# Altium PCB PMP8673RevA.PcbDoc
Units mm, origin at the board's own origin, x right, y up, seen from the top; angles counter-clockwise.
Board outline 96.52 x 68.58 mm, 4 copper layers (Top Layer, Layer2, Layer3, Bottom Layer), stack 2.424 mm thick; 65 components, 30 nets, 170 pads, 151 vias.
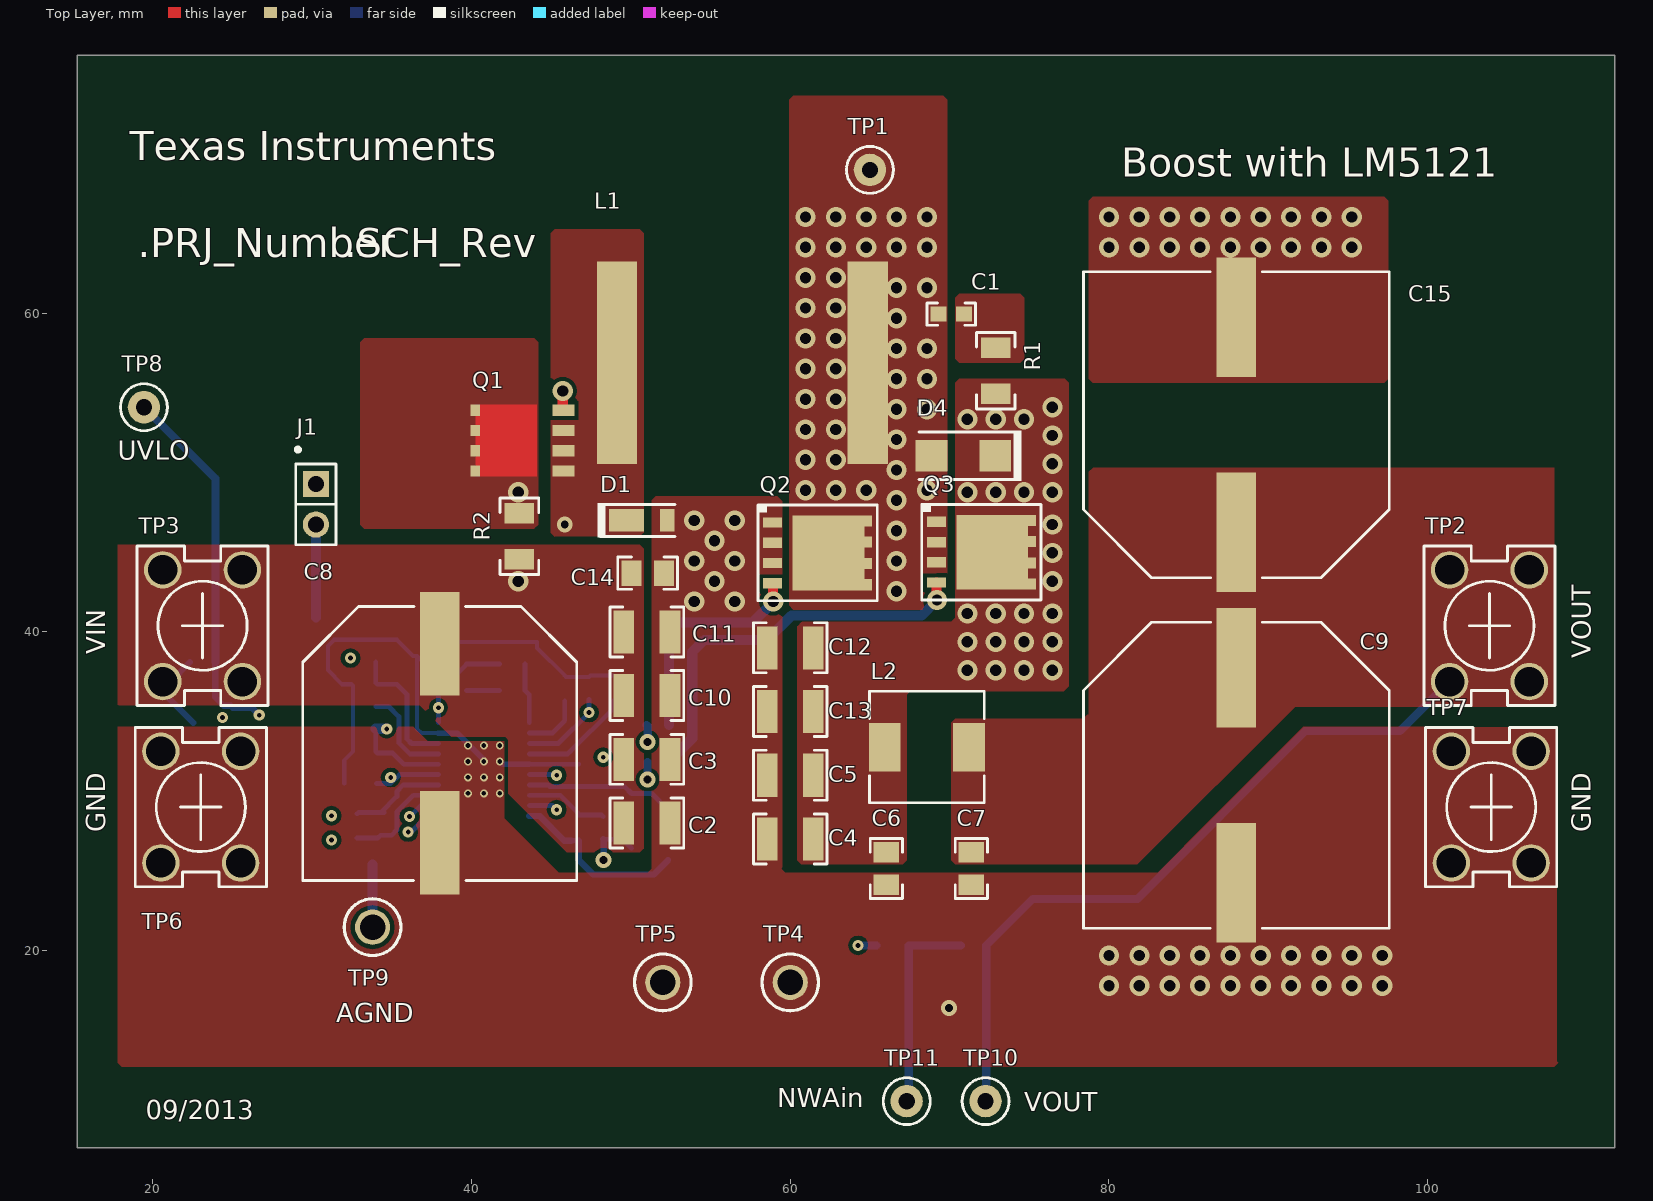
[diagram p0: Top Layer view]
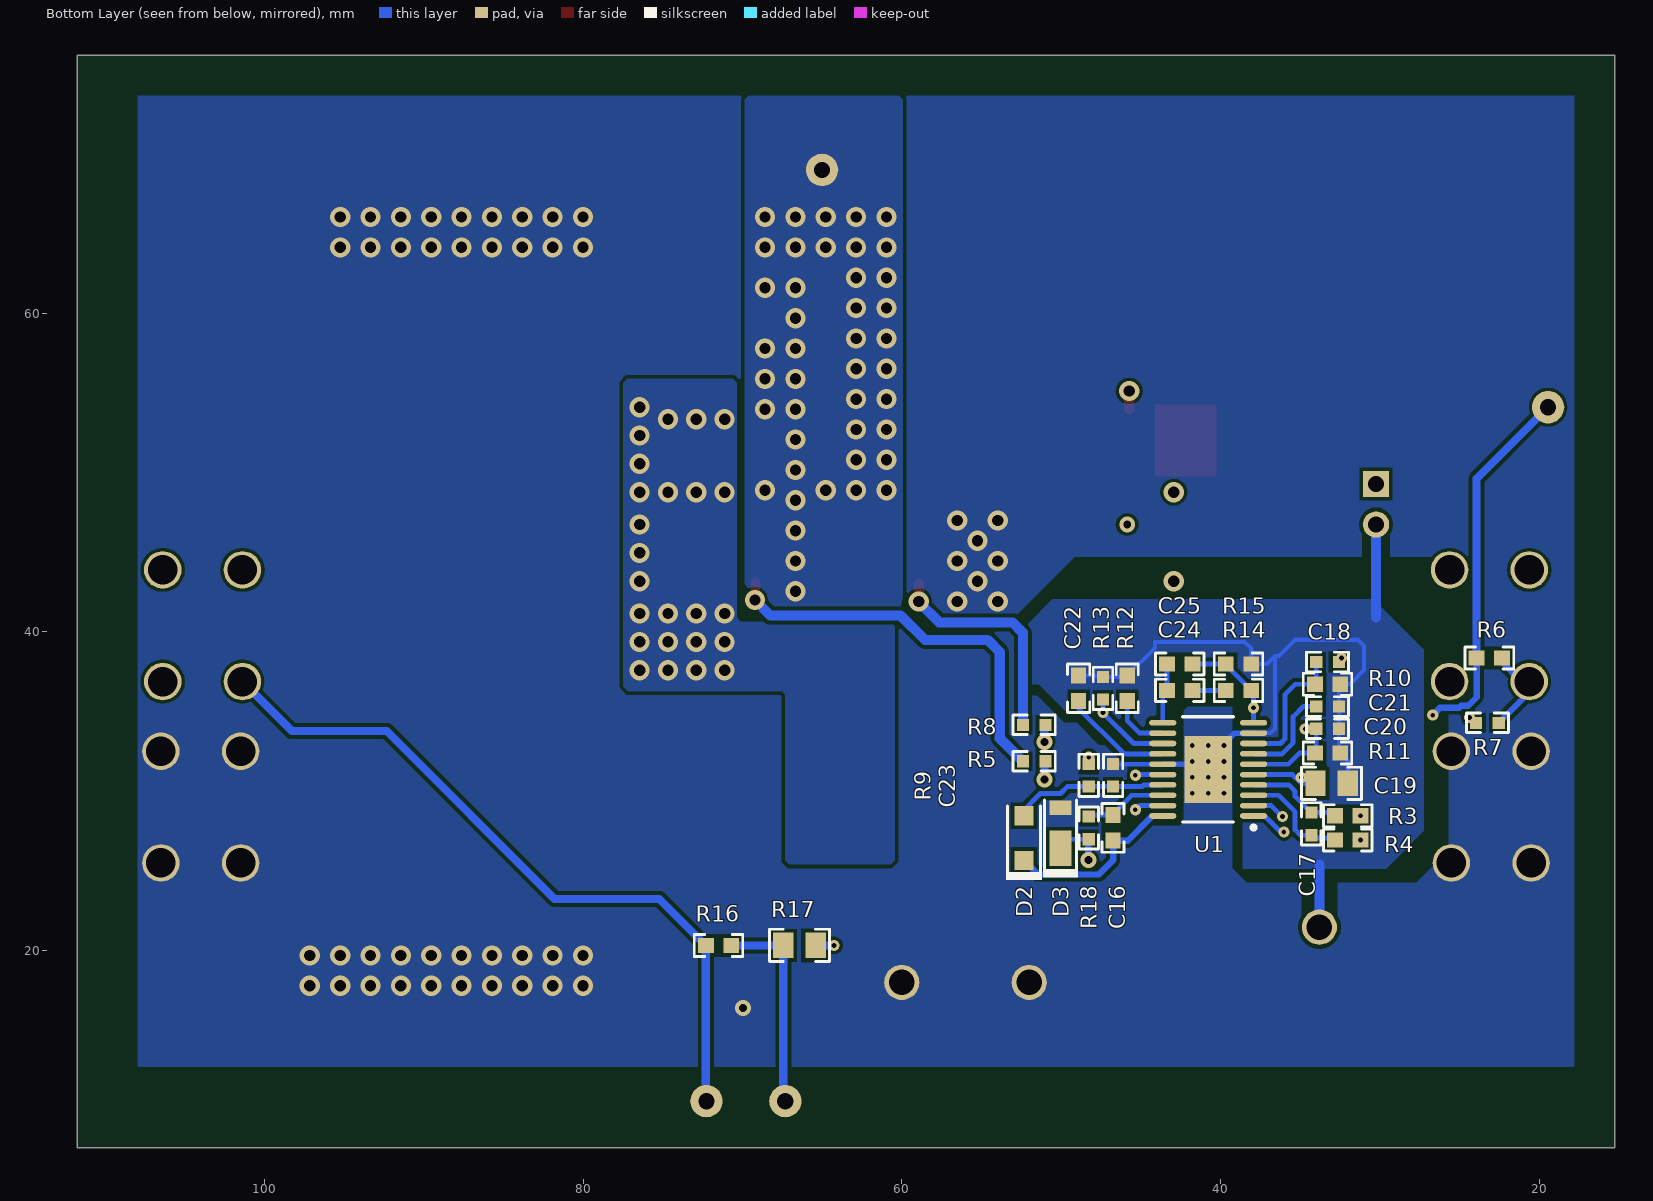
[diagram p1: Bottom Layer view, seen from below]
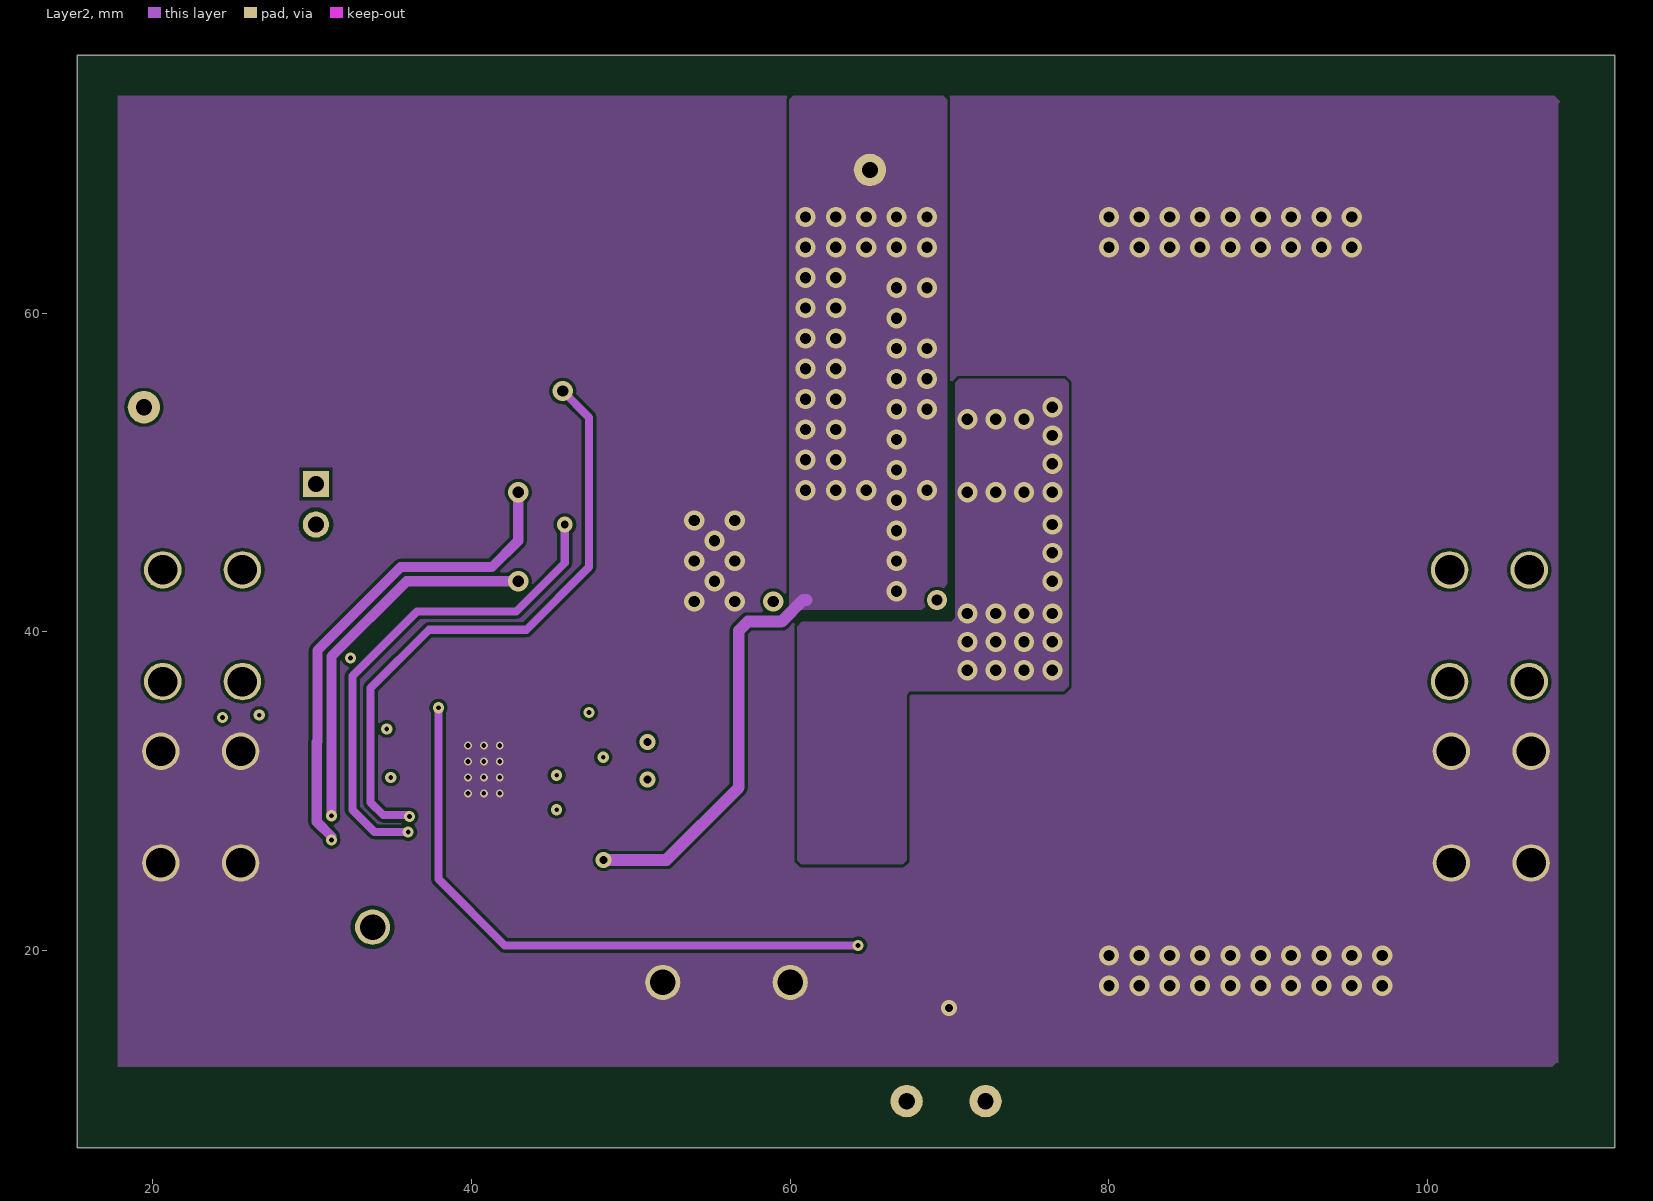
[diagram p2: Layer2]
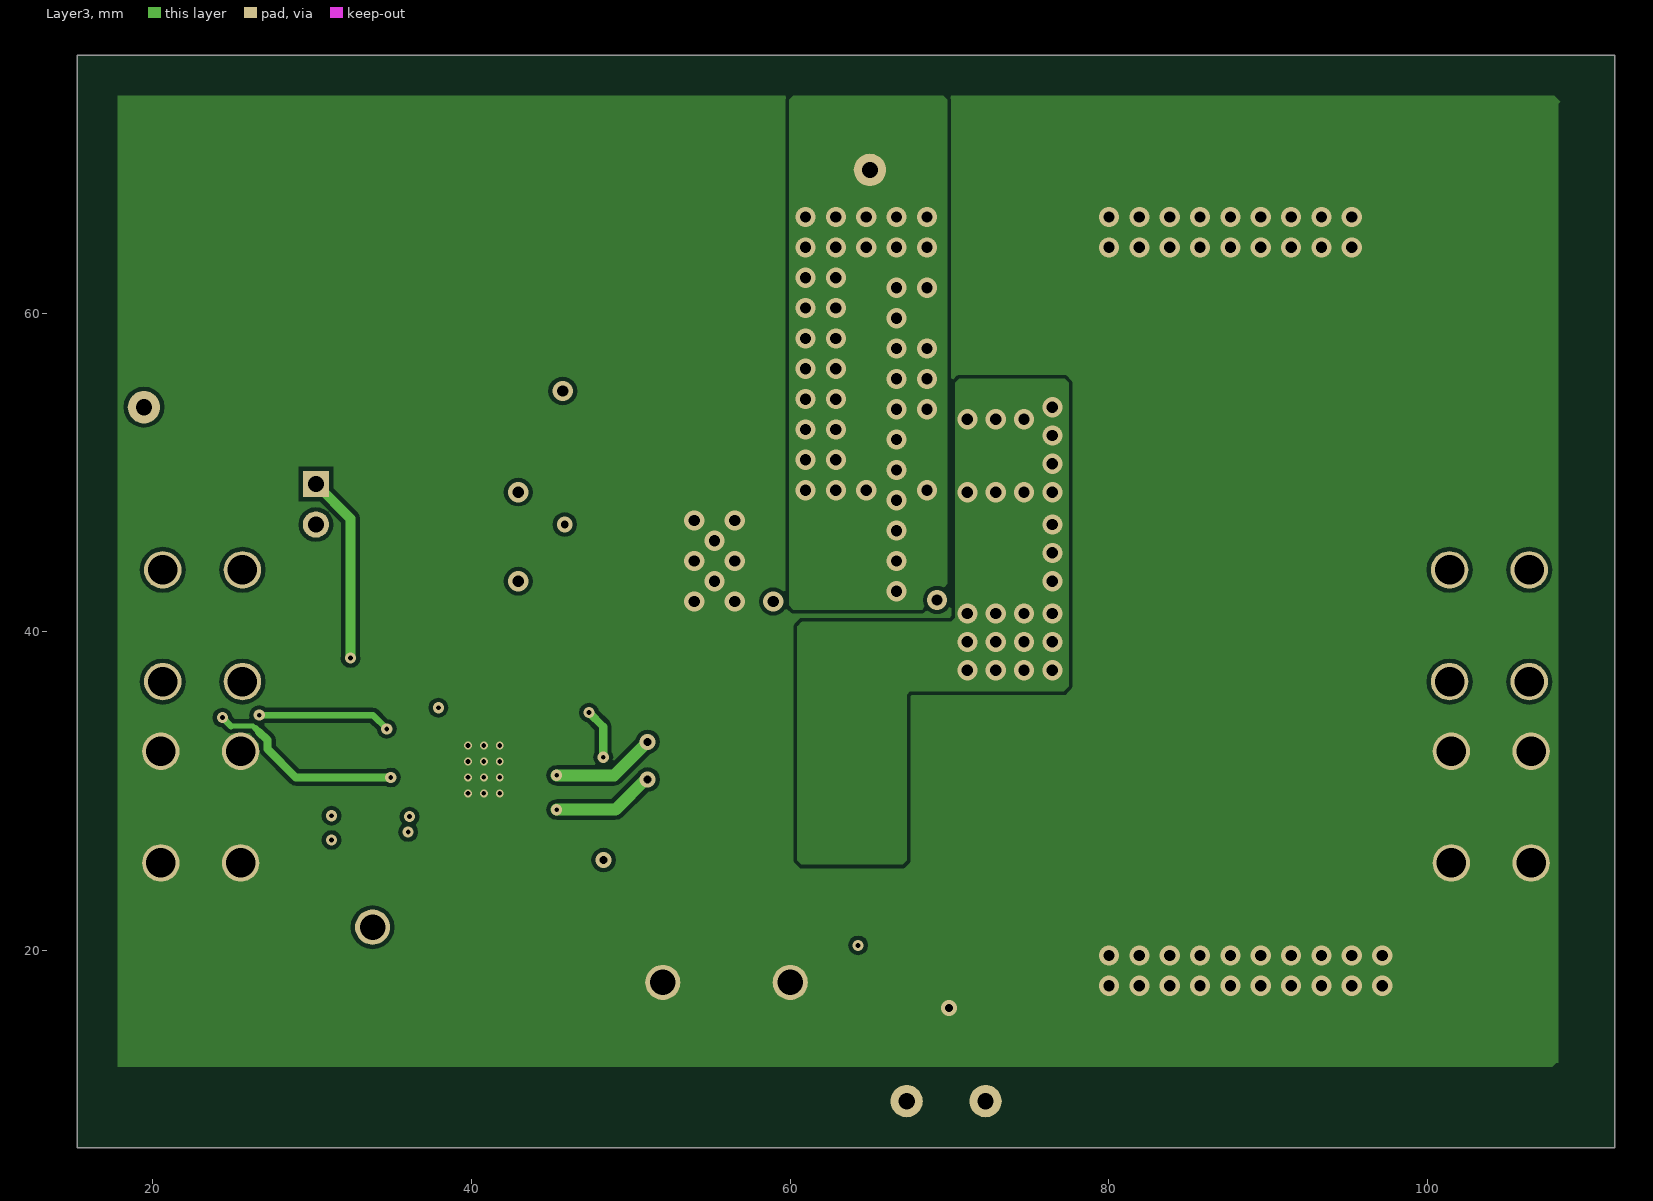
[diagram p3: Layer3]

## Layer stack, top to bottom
Top Solder: solder mask 0.0102, Solder Resist, Dk 3.5
Top Layer: signal copper 0.07
Dielectric1: core 1.5037, FR-4, Dk 4.8
Layer2: signal copper 0.07
Dielectric2: prepreg 0.32, FR-4, Dk 4.8
Layer3: signal copper 0.07
Dielectric3: core 0.32, FR-4, Dk 4.8
Bottom Layer: signal copper 0.07
Bottom Solder: solder mask 0.0102, Solder Resist, Dk 3.5

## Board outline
15.24,7.62 111.76,7.62 111.76,76.2 15.24,76.2

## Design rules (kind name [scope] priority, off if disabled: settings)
AcuteAngle [All] p1: minimum=4.50000000000000E+0001 checktracksonly=FALSE
AssemblyTestPointUsage [All] p1: valid=2
Clearance Clearance_Poly [InPolygon vs OnBottomLayer] p1: gap=0.254
Clearance Clearance_L3 [OnLayer('Layer3')] p2: gap=0.254
Clearance Clearance_L2 [(OnLayer('Layer 2'))] p3: gap=0.254
Clearance Clearance_Top [(OnLayer('Top Layer'))] p4: gap=0.254
Clearance Clearance_BoardEdge_MountingHoles [OnCopper and InComponentClass('Mounting Holes') vs IsKeepOut] p5: gap=1.016
Clearance Clearance_BoardEdge_Poly [OnCopper and InPoly vs IsKeepOut] p6: gap=0.635
Clearance Clearance_BoardEdge [OnCopper and Not InComponentClass('Logo') and not InComponentClass('FiducialMark') and not InRegion(1000,500,4000,800) and Not IsKeepout vs IsKeepOut] p7: gap=1.905
Clearance [All] p8: gap=0.201
ComponentClearance ComponentClearance_ScrewToNut [(HasFootprint('NY PMS 440 0025 PH')) vs (HasFootprint('Keystone_1902C'))] p1 off: gap=0.127 collisioncheckmode=3 verticalgap=0.254 showdistances=FALSE
ComponentClearance ComponentClearance_MountingHoles [InComponentClass('Mounting Holes')] p2 off: gap=6.35 collisioncheckmode=3 verticalgap=2540 showdistances=FALSE
ComponentClearance ComponentClearance_SmallPassives [HasFootprint('0201*') or HasFootprint('0402*') or HasFootprint('0508') or HasFootprint('0603*') or HasFootprint('0612') or HasFootprint('0805*') or HasFootprint('0815*') or HasFootprint('0830*') or HasFootprint('1206*') or HasFootprint('1210*') or HasFootprint('1808*') or HasFootprint('1812*') or HasFootprint('1825*') or HasFootprint('2010*') or HasFootprint('2220*') or HasFootprint('2225*') or HasFootprint('2512*') or HasFootprint('2728*') or HasFootprint('3518*') vs HasFootprint('0201*') or HasFootprint('0402*') or HasFootprint('0508') or HasFootprint('0603*') or HasFootprint('0612') or HasFootprint('0805*') or HasFootprint('0815*') or HasFootprint('0830*') or HasFootprint('1206*') or HasFootprint('1210*') or HasFootprint('1808*') or HasFootprint('1812*') or HasFootprint('1825*') or HasFootprint('2010*') or HasFootprint('2220*') or HasFootprint('2225*') or HasFootprint('2512*') or HasFootprint('2728*') or HasFootprint('3518*')] p3 off: gap=0.508 collisioncheckmode=3 verticalgap=0.254 showdistances=FALSE
ComponentClearance ComponentClearance_THtoSMT [IsThruComponent vs IsSMTComponent] p4 off: gap=2.54 collisioncheckmode=3 verticalgap=2540 showdistances=FALSE
ComponentClearance ComponentClearance_THtoTH [IsThruComponent vs IsThruComponent] p5 off: gap=3 collisioncheckmode=3 verticalgap=2540 showdistances=FALSE
ComponentClearance [All] p6 off: gap=1.016 collisioncheckmode=3 verticalgap=0.254 showdistances=FALSE
DiffPairsRouting [All] p1: maxlimit=2.54 minlimit=0.254 mostfreqgap=0.254 toplayer_minwidth=0.381 toplayer_maxwidth=0.381 toplayer_prefwidth=0.381 midlayer1_minwidth=0.381 midlayer1_maxwidth=0.381 midlayer1_prefwidth=0.381 midlayer2_minwidth=0.381 midlayer2_maxwidth=0.381 midlayer2_prefwidth=0.381 bottomlayer_minwidth=0.381 bottomlayer_maxwidth=0.381 bottomlayer_prefwidth=0.381 maxuncoupledlength=25.4
FabricationTestPointUsage TestPointUsage [All] p1: valid=2 allowmultiple=FALSE
FabricationTestpoint Testpoint [All] p1: side=3 testpointundercomponent=TRUE minsize=1.016 maxsize=2.54 preferedsize=1.524 minholesize=0 maxholesize=1.016 preferedholesize=0.813 testpointgrid=0.025 allowsidetop=TRUE allowsidebottom=TRUE usegrid=TRUE gridtolerance=0
FanoutControl Fanout_LCC [IsLCC] p1: bgadir=Out bgaviamode=Centered fanoutstyle=Auto fanoutdirection=Alternating viagrid=0.025 // Fanout_LCC (Default Rule)
FanoutControl Fanout_BGA [IsBGA] p2: bgadir=Out bgaviamode=Centered fanoutstyle=Auto fanoutdirection=Alternating viagrid=0.025 // Fanout_BGA (Default Rule)
FanoutControl Fanout_Default [All] p4: bgadir=Out bgaviamode=Centered fanoutstyle=Auto fanoutdirection=Alternating viagrid=0.025 // Fanout_Default (Default Rule)
FanoutControl Fanout_Small [(CompPinCount < 5)] p5: bgadir=Out bgaviamode=Centered fanoutstyle=Auto fanoutdirection=OutThenIn viagrid=0.025 // Fanout_Small (Default Rule)
HoleSize [All] p1: absolutevalues=TRUE maxlimit=6.375 minlimit=0.203 maxpercent=80.000 minpercent=20.000
MinimumAnnularRing [All] p1: minimumring=0.2
MinimumSolderMaskSliver MinimumSolderMaskSliver_Logo [InComponentClass('Logo') vs InComponentClass('Logo')] p1: minsoldermaskwidth=0.018
MinimumSolderMaskSliver [All] p2: minsoldermaskwidth=0.102
PlaneConnect [All] p1: planeconnectstyle=Relief reliefexpansion=0.254 reliefentries=4 reliefconductorwidth=0.254 reliefairgap=0.254
PolygonConnect PolygonConnect_1 [InComponent('J1') Or InComponent('TP9')] p1: connectstyle=NoConnect reliefconductorwidth=0.254 reliefentries=4 polygonreliefangle="90 Angle" airgapwidth=0.254
PolygonConnect [All] p2: connectstyle=Direct reliefconductorwidth=0.254 reliefentries=4 polygonreliefangle="90 Angle" airgapwidth=0.254
RoutingVias [All] p1: holewidth=0.406 width=0.864 viastyle="Through Hole" minholewidth=0.203 minwidth=0.66 maxholewidth=1.016 maxwidth=1.651
SMDToCorner [All] p1: distance=30000
SilkToSilkClearance [All] p1: silktosilkclearance=0.127
SilkToSolderMaskClearance SilkscreenOverComponentPads [IsPad] p1: minsilkscreentomaskgap=0.127 clearancetoexposedcopper=TRUE
SolderMaskExpansion [All] p1: expansion=0.076
UnpouredPolygon [All] p1: allowunpoured=FALSE
Width [All] p1: maxlimit=2.54 minlimit=0.152 preferedwidth=0.254 checkconnectedcopper=TRUE
15 further rules are at their usual default settings.

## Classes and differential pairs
component class Header: J1

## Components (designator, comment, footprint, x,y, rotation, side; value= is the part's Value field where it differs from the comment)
C1 "GRM188R72A331KA01D" 0603 70.104,59.944 r180 top
C2 "GRM32ER71H106KA12L" 1210 51,28 r0 top
C3 "GRM32ER71H106KA12L" 1210 51,32 r0 top
C4 "GRM32ER72A225KA35L" 1210 60,27 r180 top
C5 "GRM32ER72A225KA35L" 1210 60,31 r180 top
C6 "C2012X7R2A104K" 0805_HV 66.04,25.146 r270 top
C7 "C2012X7R2A104K" 0805_HV 71.374,25.146 r270 top
C8 "EEV-FK1J471M" SM_RADIAL_J16 38,33 r270 top
C9 "EEV-FK2A221M" SM_RADIAL_K16 88,31 r270 top
C10 "GRM32ER71H106KA12L" 1210 51,36 r0 top
C11 "GRM32ER71H106KA12L" 1210 51,40 r0 top
C12 "GRM32ER72A225KA35L" 1210 60,39 r180 top
C13 "GRM32ER72A225KA35L" 1210 60,35 r180 top
C14 "GRM21BR71H105KA12L" 0805_HV 51.054,43.688 r0 top
C15 "EEV-FK2A221M" SM_RADIAL_K16 88,53 r90 top
C16 "GRM188R71E104KA01D" 0603 46.736,27.694 r270 bottom
C17 "GRM1885C1H101JA01D" 0603_HV 34.29,27.948 r90 bottom
C18 "GRM1885C1H101JA01D" 0603_HV 33.274,38.108 r180 bottom
C19 "GRM21BR71H105KA12L" 0805_HV 33.02,30.488 r180 bottom
C20 "GRM1885C1H101JA01D" 0603_HV 33.274,33.917 r180 bottom
C21 "GRM188R71E104KA01D" 0603_HV 33.274,35.314 r180 bottom
C22 "GRM188R71E224KA88D" 0603 48.895,36.457 r90 bottom
C23 "4.7µF" 0603_HV 46.736,30.996 r90 bottom
C24 "C0603C682J5RACTU" 0603 42.545,36.33 r180 bottom
C25 "C0603C680J5GACTU" 0603 42.545,37.981 r180 bottom
D1 "DFLS1100-7" powerDI123 51,47 r0 top
D2 "PMEG6010CEH,115" SOD-123F 52.324,27.059 r90 bottom
D3 "DFLS1100-7" powerDI123 50.038,27.694 r90 bottom
D4 "B180-13-F" SMA 70.866,51.054 r180 top
J1 "TSW-102-07-G-S" TSW-102-07-G-S 30.226,48.006 r270 top
L1 "IHLP-6767GZ-5A" IND_VISHAY_675_X_675 57,56.896 r0 top
L2 "744302010" IND_WE-HCM_7050 68.58,32.766 r0 top
Q1 "CSD18532Q5B" TRANS_NexFET_Q5B 43,52 r180 top
Q2 "BSC340N08NS3 G" PG-TDSON-8 61.722,44.958 r0 top
Q3 "BSC123N08NS3 G" PG-TDSON-8 72,45 r0 top
R1 "CRCW120610R0JNEA" 1206 72.898,56.388 r270 top
R2 "LVK12R010DER" 1206 43,46 r90 top
R3 "CRCW0603100RFKEA" 0603 32.004,28.456 r0 bottom
R4 "CRCW0603100RFKEA" 0603 32.004,26.932 r0 bottom
R5 "ERJ-3GEY0R00V" 0603_HV 51.689,31.877 r180 bottom
R6 "CRCW0603200KFKEA" 0603 23.114,38.354 r180 bottom
R7 "CRCW06033R30JNEA" 0603_HV 23.241,34.29 r180 bottom
R8 "ERJ-3GEY0R00V" 0603_HV 51.689,34.163 r0 bottom
R9 "ERJ-3GEY0R00V" 0603_HV 48.26,30.996 r270 bottom
R10 "CRCW060322K6FKEA" 0603 33.274,36.711 r0 bottom
R11 "CRCW06037K32FKEA" 0603 33.274,32.393 r0 bottom
R12 "CRCW060356K2FKEA" 0603 45.847,36.457 r270 bottom
R13 "ERJ-3GEY0R00V" 0603_HV 47.371,36.457 r270 bottom
R14 "CRCW060356K2FKEA" 0603 38.862,36.33 r180 bottom
R15 "CRCW06032K21FKEA" 0603 38.862,37.981 r180 bottom
R16 "CRCW060349K9FKEA" 0603 71.501,20.32 r180 bottom
R17 "CRCW0805100KFKEA" 0805_HV 66.421,20.32 r180 bottom
R18 "ERJ-3GEY0R00V" 0603_HV 48.26,27.694 r90 bottom
TP1 "5002" Keystone5002 65,69 r0 top
TP2 "7693" 7693 103.886,40.386 r180 top
TP3 "7693" 7693 23.114,40.386 r0 top
TP4 "5011" Keystone5011 60,18 r0 top
TP5 "5011" Keystone5011 52,18 r0 top
TP6 "7693" 7693 23,29 r180 top
TP7 "7693" 7693 104,29 r180 top
TP8 "5002" Keystone5002 19.431,54.102 r180 top
TP9 "5011" Keystone5011 33.782,21.463 r180 top
TP10 "5002" Keystone5002 72.263,10.541 r180 top
TP11 "5002" Keystone5002 67.31,10.541 r180 top
U1 "LM5121MH/NOPB" PWP0020A_N 40.767,31.369 r0 bottom

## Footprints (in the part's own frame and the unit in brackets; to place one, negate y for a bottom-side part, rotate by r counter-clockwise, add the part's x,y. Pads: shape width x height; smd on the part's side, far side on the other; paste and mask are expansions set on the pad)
0603 [mm] "0603 from SM-752 data"
  rect 1x0.95 smd: 1(-0.8,0) 2(0.8,0)
  silkscreen extent -1.52,-0.69 1.52,0.69, body extent -0.87,-0.47 0.87,0.47, height 0.85
0603_HV [mil] "Ernesto recommended land pattern.  26 mil between pads."
  rect 30x30 smd: 1(-28,0) 2(28,0)
  silkscreen extent -52,-24 52,24, body extent -34,-19 34,19, height 33
0805_HV [mil] "0805 with 30mil clearance between pads"
  rect 50x63 smd: 1(-40,0) 2(40,0)
  silkscreen extent -74,-40 74,40, body extent -43,-29 43,29, height 43
1206 [mm] "1206 from SM-752 data"
  rect 1.3x1.85 smd: 1(-1.45,0) 2(1.45,0)
  silkscreen extent -2.4,-1.21 2.4,1.21, body extent -1.7,-0.9 1.7,0.9, height 1.35
1210 [mm] "1210 from SM-752 data"
  rect 1.3x2.7 smd: 1(-1.45,0) 2(1.45,0)
  silkscreen extent -2.32,-1.57 2.32,1.57, body extent -1.7,-1.35 1.7,1.35, height 1.35
7693 [mm] "Keystone Electronics 7693 recommended land pattern"
  round 2.35 hole 1.85: 1(-2.502,3.505) 2(2.502,3.505) 3(-2.502,-3.505) 4(2.502,-3.505)
  silkscreen extent -4.11,-5 4.11,5, body extent -3.95,-3.94 3.95,3.96, height 8.86
IND_VISHAY_675_X_675 [mil]
  rect 100x500 smd: 1(-310,0) 2(310,0)
IND_WE-HCM_7050 [mm] "WURTH ELEKTRONIK"
  rect 2x3.05 smd: 1(-2.65,0) 2(2.65,0)
  silkscreen extent -3.6,-3.5 3.6,3.5, body extent -3.57,-3.5 3.57,3.5, height 5
Keystone5002 [mil] "For Keystone 500x miniature loop terminals"
  round 80 hole 40: 1(0,0)
  silkscreen extent -58,-58 58,58, body extent -49,-49 49,49, height 182
Keystone5011 [mil] "Keystone Multipurpose loops"
  round 87 hole 63: 1(0,0)
  silkscreen extent -70,-70 70,70, body extent -63,-63 63,62, height 319
PG-TDSON-8 [mm] "Infineon recommended land pattern"
  rect 1.2x0.65 smd: 1(-2.825,1.905) 2(-2.825,0.635) 3(-2.825,-0.635) 4(-2.825,-1.905)
  rect 0.5x0.7 smd: 5(3.175,-2) 6(3.175,-0.675) 7(3.175,0.675) 8(3.175,2)
  rect 4.5x4.7 smd paste-2.25: 9(0.675,0)
  silkscreen extent -3.74,-3 3.74,3, body extent -3.17,-2.89 3.17,2.9, height 1.1
powerDI123 [mm] "Diodes Inc recommended land pattern, document number DS30628 Rev. 6-2"
  rect 2.2x1.4 smd: 1(-1.275,0)
  rect 0.9x1.4 smd: 2(1.275,0)
  silkscreen extent -3.1,-1.09 1.76,1.09, body extent -2.38,-0.97 1.52,0.96, height 1
PWP0020A_N [mm] "TSOP, 20-Leads, Body 6.5x4.4mm, Pitch 0.65mm, Exposed Pad, IPC Medium Density"
  oval 1.7x0.35 smd: 1(-2.85,2.925) 2(-2.85,2.275) 3(-2.85,1.625) 4(-2.85,0.975) 5(-2.85,0.325) 6(-2.85,-0.325) 7(-2.85,-0.975) 8(-2.85,-1.625) 9(-2.85,-2.275) 10(-2.85,-2.925) 11(2.85,-2.925) 12(2.85,-2.275) 13(2.85,-1.625) 14(2.85,-0.975) 15(2.85,-0.325) 16(2.85,0.325) 17(2.85,0.975) 18(2.85,1.625) 19(2.85,2.275) 20(2.85,2.925)
  rect 3x4.2 smd: 21(0,0)
  silkscreen extent -2.97,-3.3 1.6,3.77, body extent -2.25,-3.3 2.25,3.3, height 1.1
SM_RADIAL_J16 [mm] "16 x 16.5mm:  Panasonic J16"
  rect 6.5x2.5 smd: 1(-6.25,0) 2(6.25,0)
  silkscreen extent -8.6,-8.6 8.6,8.6, body extent -8.6,-8.6 8.6,8.6, height 17
SM_RADIAL_K16 [mm] "18 x 16.5mm:  Panasonic K16 (K18 from land pattern recommendation)"
  rect 7.5x2.5 smd: 1(-6.75,0) 2(6.75,0)
  silkscreen extent -9.6,-9.6 9.6,9.6, body extent -9.6,-9.6 9.6,9.6, height 17
SMA [mm] "Molded Diode, 2-Leads, Body 4.3x2.6mm, IPC Medium Density, based on OnSemi component dimensions and land pattern"
  rect 2x2 smd: 1(-2,0) 2(2,0)
  silkscreen extent -3.66,-1.57 2.79,1.57, body extent -2.6,-1.3 2.6,1.3, height 2.42
SOD-123F [mm] "NXP recommended land pattern"
  rect 1.2x1.2 smd paste-0.05: 1(-1.4,0) 2(1.4,0)
  silkscreen extent -2.64,-1.12 2.01,1.12, body extent -1.8,-0.85 1.8,0.85, height 1.2
TRANS_NexFET_Q5B [mm] "TI recommended land pattern (nominal) November 2012"
  rect 1.372x0.71 smd paste-0.4 mask+0.051: 1(-2.776,1.905) 2(-2.776,0.635) 3(-2.776,-0.635) 4(-2.776,-1.905)
  rect 0.59x0.71 smd paste-0.3: 5(2.776,-1.905) 6(2.776,-0.635) 7(2.776,0.635) 8(2.776,1.905)
  Top Layer region: -1.106,-2.26 2.744,-2.26 2.744,2.26 -1.106,2.26
  body extent -3.23,-2.55 2.87,2.55, height 1.06
TSW-102-07-G-S [mm] "Samtec 100mil, 1x2, 230 mil above insulator"
  rect 1.65x1.65 hole 1.016 mask+0: 1(-1.27,0)
  round 1.65 hole 1.016 mask+0: 2(1.27,0)
  silkscreen extent -3.56,-1.27 2.54,1.27, body extent -2.54,-1.27 2.54,1.27, height 8.38

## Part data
C1: "CAP, CERM, 330pF, 100V, +/-10%, X7R, 0603"
C2 C3 C10 C11: "CAP, CERM, 10uF, 50V, +/-10%, X7R, 1210"
C4 C5 C12 C13: "CAP, CERM, 2.2uF, 100V, +/-10%, X7R, 1210"
C6 C7: "CAP, CERM, 0.1uF, 100V, +/-10%, X7R, 0805"
C8: "CAP, AL, 470uF, 63V, +/-20%, 0.082 ohm, SMD"
C9 C15: "CAP, AL, 220uF, 100V, +/-20%, 0.153 ohm, SMD"
C14 C19: "CAP, CERM, 1uF, 50V, +/-10%, X7R, 0805"
C16 C21: "CAP, CERM, 0.1uF, 25V, +/-10%, X7R, 0603"
C17 C18 C20: "CAP, CERM, 100pF, 50V, +/-5%, C0G/NP0, 0603"
C22: "CAP, CERM, 0.22uF, 25V, +/-10%, X7R, 0603"
C23: library part C1608X6S1A475K, "CAP CER 4.7UF 10V 10% X6S 0603"
C24: "CAP, CERM, 6800pF, 50V, +/-5%, X7R, 0603"
C25: "CAP, CERM, 68pF, 50V, +/-5%, C0G/NP0, 0603"
D1 D3: "Diode, Schottky, 100V, 1A, PowerDI123"
D2: "Diode, Schottky, 60V, 1A, SOD-123F"
D4: "Diode, Schottky, 80V, 1A, SMA"
J1: "Header, TH, 100mil, 2x1, Gold plated, 230 mil above insulator"
L1: library part IND_IHLP-6767_SERIES, "Inductor, 22.3milliOhm, 11Asat, ±20% @ 100KHz"
L2: "Inductor, Shielded Drum Core, Ferrite, 105nH, 30A, 0.000235 ohm, SMD"
Q1: "MOSFET, N-CH, 60V, 172A, SON 5x6mm"
Q2: "MOSFET, N-CH, 80V, 23A, PG-TDSON-8"
Q3: "MOSFET, N-CH, 80V, 55A, PG-TDSON-8"
R1: "RES, 10 ohm, 5%, 0.25W, 1206"
R2: "RES, 0.01 ohm, 0.5%, 0.5W, 1206"
R3 R4: "RES, 100 ohm, 1%, 0.1W, 0603"
R5 R8 R9 R13 R18: "RES, 0 ohm, 5%, 0.1W, 0603"
R6: "RES, 200k ohm, 1%, 0.1W, 0603"
R7: "RES, 3.3 ohm, 5%, 0.1W, 0603"
R10: "RES, 22.6k ohm, 1%, 0.1W, 0603"
R11: "RES, 7.32k ohm, 1%, 0.1W, 0603"
R12 R14: "RES, 56.2k ohm, 1%, 0.1W, 0603"
R15: "RES, 2.21k ohm, 1%, 0.1W, 0603"
R16: "RES, 49.9k ohm, 1%, 0.1W, 0603"
R17: "RES, 100k ohm, 1%, 0.125W, 0805"
TP1 TP8 TP10 TP11: "Test Point, TH, Miniature, White"
TP2 TP3 TP6 TP7: "Terminal screw, vertical, snap-in"
TP4 TP5 TP9: "Test Point, TH, Multipurpose, Black"
U1: "Wide Input Synchronous Boost Controller with Disconnection Switch Control, PWP0020A"

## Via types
v1: diameter 1.27, hole 0.711, Top Layer to Bottom Layer, 119 vias
v2: diameter 0.7, hole 0.3, Top Layer to Bottom Layer, tented both sides, 15 vias
v3: diameter 0.5, hole 0.3, Top Layer to Bottom Layer, 12 vias
v4: diameter 1, hole 0.5, Top Layer to Bottom Layer, tented both sides, 5 vias

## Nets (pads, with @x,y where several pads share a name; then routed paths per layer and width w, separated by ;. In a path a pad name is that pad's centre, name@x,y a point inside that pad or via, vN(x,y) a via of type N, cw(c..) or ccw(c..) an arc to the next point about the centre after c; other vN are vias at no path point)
+VIN: C2.1 C3.1 C8.1 C10.1 C11.1 C14.1 R2.1 R3.1 R6.2 R7.2 TP3.1 TP3.2 TP3.3 TP3.4 | length 29.3
  Layer2 w0.635: v2(31.204,28.456) 31.204,38.462 35.922,43.18 v1(42.926,43.18)
  Bottom Layer w0.4: R6.2@22.314,38.1 21.095,36.881 TP3.3 20.612,36.208 R7.2
+VOUT: C7.1 C9.1 C15.1 L2.2 R16.1 TP2.1 TP2.2 TP2.3 TP2.4 TP10.1 | length 45.7
  Bottom Layer w0.508: TP10.1 72.301,10.579 R16.1 75.222,23.241 81.788,23.241 92.329,33.782 98.285,33.782 TP2.2
CS_N: Q1.5 Q1.6 Q1.7 Q1.8 R2.2 R4.1 | length 30.8
  Layer2 w0.635: v2(31.204,26.932) 31.204,27.153 30.282,28.074 30.282,33.076 30.315,33.109 30.315,38.83 35.554,44.069 41.275,44.069 42.926,45.72 v1(42.926,48.768)
DG: Q1.4 U1.2 | length 41.8
  Top Layer w0.635: Q1.4@45.72,53.961 v1(45.72,55.118)
  Layer2 w0.508: v2(36.103,28.406) 36.011,28.497 34.452,28.497 33.655,29.294 33.655,36.47 37.317,40.132 43.434,40.132 47.371,44.069 47.371,53.467 v1(45.72,55.118)
  Bottom Layer w0.305: v2@36.117,28.406 36.805,29.094 U1.2
DS: D1.1 L1.1 Q1.1 Q1.2 Q1.3 U1.1 | length 33.3
  Layer2 w0.508: v2(36.017,27.432) 33.902,27.432 32.512,28.822 32.512,37.219 36.568,41.275 42.799,41.275 45.847,44.323 v4(45.847,46.736)
  Bottom Layer w0.305: v2@36.195,27.432 37.207,28.444 U1.1
HO: Q3.4 R5.1 | length 25.2
  Top Layer w0.635: v1@69.175,42.04 Q3.4
  Bottom Layer w0.635: R5.1 53.848,33.325 53.848,38.735 54.61,39.497 58.547,39.497 60.071,41.021 68.236,41.021 v1(69.215,42)
LO: Q2.4 R8.2 | length 14.4
  Top Layer w0.254: Q2.4@58.706,43.053 Q2.4
  Top Layer w0.635: v1(58.928,41.91) Q2.4@58.928,43.022
  Bottom Layer w0.635: R8.2 52.4,39.95 53.05,40.6 57.65,40.6 v1@58.928,41.878
NetC1_1: C1.1 R1.1
NetC4_1: C4.1 C5.1 C6.1 C12.1 C13.1 D4.1 L2.1 Q3.5 Q3.6 Q3.7 Q3.8 Q3.9 R1.2
  other v1: 71.12,37.592 72.898,37.592 74.676,37.592 76.454,37.592 71.12,39.37 72.898,39.37 74.676,39.37 76.454,39.37 71.12,41.148 72.898,41.148 74.676,41.148 76.454,41.148 76.454,43.18 76.454,44.958 76.454,46.736 71.12,48.768 72.898,48.768 74.676,48.768 76.454,48.768 76.454,50.546 76.454,52.324 71.12,53.34 72.898,53.34 74.676,53.34 76.454,54.102
NetC16_1: C16.1 R18.2 U1.18 | length 5.2
  Bottom Layer w0.305: U1.18 45.575,29.744 46.736,28.583 C16.1 48.171,28.494 R18.2
NetC16_2: C16.2 D2.1 U1.20 | length 11.3
  Bottom Layer w0.305: C16.2@46.266,26.894 C16.2
  Bottom Layer w0.4: U1.20 44.268,28.444 45.818,26.894 C16.2@46.266,26.894 ; C16.2 46.736,25.662 47.625,24.773 51.438,24.773 D2.1
NetC17_1: C17.1 R4.2 U1.3 | length 6.9
  Bottom Layer w0.305: R4.2@32.804,27.059 34.112,27.059 C17.1 34.976,27.237 35.306,27.567 35.306,28.71 36.34,29.744 U1.3
NetC17_2: C17.2 R3.2 U1.4 | length 6.2
  Bottom Layer w0.305: R3.2@32.804,28.583 32.88,28.659 C17.2 ; C17.2@34.493,28.659 C17.2 ; U1.4 35.72,30.394 35.306,29.98 35.306,29.675 C17.2
NetC18_1: C18.1 R10.2 U1.8 | length 8.5
  Bottom Layer w0.305: C18.1 33.985,36.8 R10.2 35.306,36.711 35.941,36.076 35.941,33.282 36.229,32.994 U1.8
NetC18_2: C18.2 J1.1 | length 11.8
  Layer3 w0.635: J1.1 32.399,47.103 v2(32.399,38.354)
NetC19_1: C19.1 R7.1 U1.5 | length 16.6
  Layer3 w0.305: 24.895,34.087 26.286,34.087 26.357,34.016 26.371,34.016 26.419,33.969
  Layer3 w0.4: v2(24.359,34.62) 24.895,34.083 ; 26.419,33.969 26.663,33.724
  Layer3 w0.508: 26.663,33.724 27.185,33.202 27.185,32.639 28.963,30.861 v2(34.925,30.861)
  Bottom Layer w0.305: C19.1 34.925,30.488 35.481,31.044 U1.5
NetC20_1: C20.1 R6.1 R11.2 TP8.1 U1.6 | length 38
  Layer3 w0.4: v2(26.67,34.773) 33.807,34.773 v2(34.671,33.909)
  Bottom Layer w0.305: C20.1 33.985,32.482 R11.2 35.052,32.393 35.751,31.694 U1.6
  Bottom Layer w0.4: R6.1@23.914,38.1 23.914,35.903 24.444,35.373 24.891,35.373 25.016,35.249 26.194,35.249 v2(26.67,34.773)
  Bottom Layer w0.5: TP8.1 23.914,49.619 R6.1@23.914,38.1
  Bottom Layer w0.635: C20.1 v2@34.663,33.917
NetC21_1: C21.1 U1.7 | length 6.1
  Bottom Layer w0.305: C21.1 34.798,35.314 35.433,34.679 35.433,33.072 ; 35.433,33.028 36.117,32.344 U1.7
NetC22_1: C22.1 U1.14 | length 6.9
  Bottom Layer w0.305: U1.14 46.036,32.344 46.187,32.495 46.203,32.495 48.895,35.187 C22.1
NetC24_1: C24.1 C25.1 U1.11 | length 3.8
  Bottom Layer w0.305: C25.1 C24.1 43.617,36.058 U1.11
NetC24_2: C24.2 R14.1 | length 2.1
  Bottom Layer w0.305: R14.1 C24.2
NetC25_2: C25.2 R14.2 R15.1 R17.2 U1.10 | length 46.5
  Layer2 w0.508: v2(37.917,35.239) 37.917,24.482 42.079,20.32 v2(64.262,20.32)
  Bottom Layer w0.254: R14.2@37.917,36.185 R14.2
  Bottom Layer w0.3: U1.10 v2(37.917,35.239) R14.2@37.917,36.185
  Bottom Layer w0.305: R14.2 39.662,37.93 R15.1 C25.2
  Bottom Layer w0.508: v2(64.262,20.32) R17.2
NetR5_2: R5.2 U1.19 | length 9.2
  Layer3 w0.75: v2(45.339,28.837) 49.03,28.837 51.029,30.836 51.054,30.81 51.054,30.73 v4(51.046,30.73)
  Bottom Layer w0.305: U1.19 45.082,29.094
  Bottom Layer w0.5: R5.2@51.029,31.826 51.029,30.836 51.054,30.81 51.054,30.73 v4(51.046,30.73)
NetR8_1: R8.1 U1.16 | length 9.4
  Layer3 w0.75: v2(45.339,30.996) 48.954,30.996 51.054,33.096 v4(51.046,33.096)
  Bottom Layer w0.305: U1.16 45.291,31.044 v2(45.339,30.996)
  Bottom Layer w0.508: R8.1 51.054,34.087 51.054,33.096 v4(51.046,33.096)
NetR9_1: R9.1 R13.2 U1.13 | length 8.5
  Layer3 w0.508: v2(47.371,34.933) 48.26,34.044 v2(48.26,32.131)
  Bottom Layer w0.305: U1.13 45.432,32.994 v2(47.371,34.933) R13.2
NetR12_2: R12.2 U1.12 | length 3.8
  Bottom Layer w0.305: U1.12 45.066,33.644 45.847,34.425 R12.2
NetR16_2: R16.2 R17.1 TP11.1 | length 13.1
  Bottom Layer w0.508: TP11.1 67.437,10.668 R17.1 R16.2
SGND: C2.2 C3.2 C4.2 C5.2 C6.2 C7.2 C8.2 C9.2 C10.2 C11.2 C12.2 C13.2 C14.2 C15.2 C19.2 C20.2 C21.2 C22.2 C23.2 D1.2 D3.2 J1.2 Q2.1 Q2.2 Q2.3 R10.1 R11.1 R12.1 R13.1 R15.2 TP4.1 TP5.1 TP6.1 TP6.2 TP6.3 TP6.4 TP7.1 TP7.2 TP7.3 TP7.4 TP9.1 U1.9 U1.15 U1.21 | length 55
  Bottom Layer w0.254: C19.2 32.004,31.923 R11.1 32.563,32.482 C20.2 C21.2 32.563,36.622 R10.1 31.877,36.711 30.988,37.6 30.988,39.124 31.369,39.505 35.306,39.505 36.322,38.489 36.576,38.489 ; U1.9 36.849,33.644 36.576,33.917 36.576,38.489 ; C23.2@46.723,31.694 C23.2 ; C22.2 47.46,37.257 R13.1 45.936,37.168 R12.1 44.107,38.997 44.107,39.378 38.481,39.378 38.062,38.959 R15.2 37.084,37.981 36.576,38.489
  Bottom Layer w0.29: U1.15 C23.2@46.723,31.694
  Bottom Layer w0.35: U1.9 39.097,33.644 U1.21@40.767,31.974 ; U1.21@41.942,31.694 U1.15
  Bottom Layer w0.635: 30.226,40.894 J1.2 ; TP9.1 33.782,25.4
  other v1: 80.01,17.78 81.915,17.78 83.82,17.78 85.725,17.78 87.63,17.78 89.535,17.78 91.44,17.78 93.345,17.78 95.25,17.78 97.155,17.78 80.01,19.685 81.915,19.685 83.82,19.685 85.725,19.685 87.63,19.685 89.535,19.685 91.44,19.685 93.345,19.685 95.25,19.685 97.155,19.685 53.975,41.91 56.515,41.91 55.245,43.18 53.975,44.45 56.515,44.45 55.245,45.72 53.975,46.99 56.515,46.99 80.01,64.135 81.915,64.135 83.82,64.135 85.725,64.135 87.63,64.135 89.535,64.135 91.44,64.135 93.345,64.135 95.25,64.135 80.01,66.04 81.915,66.04 83.82,66.04 85.725,66.04 87.63,66.04 89.535,66.04 91.44,66.04 93.345,66.04 95.25,66.04
  other v3: 39.767,29.869 40.767,29.869 41.767,29.869 39.767,30.869 40.767,30.869 41.767,30.869 39.767,31.869 40.767,31.869 41.767,31.869 39.767,32.869 40.767,32.869 41.767,32.869
  other v4: 69.977,16.383
SW: C1.2 D3.1 D4.2 L1.2 Q2.5 Q2.6 Q2.7 Q2.8 Q2.9 Q3.1 Q3.2 Q3.3 R18.1 TP1.1 | length 28.6
  Layer2 w0.75: v4(48.285,25.679) 52.222,25.679 56.769,30.226 56.769,40.081 57.334,40.646 59.452,40.646 60.817,42.012 61.011,42.012
  Bottom Layer w0.305: R18.1 49.474,26.983 D3.1
  Bottom Layer w0.4: R18.1 48.285,26.957 v4(48.285,25.679)
  other v1: 66.675,42.545 66.675,44.45 66.675,46.355 66.675,48.26 60.96,48.895 62.865,48.895 64.77,48.895 68.58,48.895 66.675,50.165 60.96,50.8 62.865,50.8 66.675,52.07 60.96,52.705 62.865,52.705 66.675,53.975 68.58,53.975 60.96,54.61 62.865,54.61 66.675,55.88 68.58,55.88 60.96,56.515 62.865,56.515 66.675,57.785 68.58,57.785 60.96,58.42 62.865,58.42 66.675,59.69 60.96,60.325 62.865,60.325 66.675,61.595 68.58,61.595 60.96,62.23 62.865,62.23 60.96,64.135 62.865,64.135 64.77,64.135 66.675,64.135 68.58,64.135 60.96,66.04 62.865,66.04 64.77,66.04 66.675,66.04 68.58,66.04
VCC: C23.1 D2.2 R9.2 U1.17 | length 9.4
  Bottom Layer w0.305: U1.17 44.798,30.394 44.902,30.29 46.73,30.29 C23.1 49.606,30.285 50.038,29.853 51.308,29.853 D2.2@52.324,28.837

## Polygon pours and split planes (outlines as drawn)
SGND on Top Layer "Top Layer-sgnd pp" (solid, remove dead copper, pour order 52): 42.037,27.686 42.037,33.147 36.817,33.147
SGND on Top Layer "SGND_top" (solid, pour order 47): 17.78,34.036 17.78,12.954 18.034,12.7 36.576,12.7 79.502,12.7 107.95,12.7 108.204,12.954 108.115,13.043 108.115,34.004 99.885,34.004 99.853,34.036 97.6,34.036 92.202,34.036 86.36,28.194 83.058,24.892 65.315,24.892 59.69,24.892 59.436,25.146 59.5,25.21 59.5,31 59.5,48.196 59.436,48.26 59.182,48.514 51.816,48.514 51.562,48.514 51.308,48.26 51.308,43.18 51.308,26.4 51.308,25.146 51.054,24.892 46.6,24.892 45.466,24.892 36.322,34.036 27.94,34.036
SW on Top Layer "SW_top" (solid, pour order 51): 59.944,47.244 59.944,41.656 60.198,41.402 68.072,41.402 69.596,41.402 69.85,41.656 69.85,48.26 69.85,65.024 69.85,71.374 69.85,73.406 69.596,73.66 60.198,73.66 59.944,73.406 59.944,44.704
DS on Top Layer "DS_top" (solid, pour order 60): 50.575,46.035 50.768,46.228 50.8,46.228 50.8,48.768 50.8,65.024 50.546,65.278 45.212,65.278 44.958,65.024 44.958,52.578 44.958,46.228 45.212,45.974
+VOUT on Top Layer "+Vout_top" (solid, pour order 59): 70.358,25.4 70.104,25.654 70.104,34.29 70.358,34.544 73.66,34.544 78.4,34.544 78.654,34.798 78.74,34.798 78.74,35.56 78.74,39.624 78.74,50.038 79.014,50.312 79.138,50.312 89.896,50.312 89.916,50.292 107.95,50.292 107.95,35.433 108.001,35.382 107.925,35.306 92.202,35.306 91.694,35.306 81.788,25.4
NetC4_1 on Top Layer "NetC4_1" (solid, pour order 57): 60.452,40.35 60.456,40.35 60.706,40.6 60.746,40.64 69.596,40.64 70.104,40.64 70.358,40.894 70.358,55.626 70.612,55.88 77.216,55.88 77.47,55.626 77.47,41.91 77.47,36.576 77.216,36.322 77.16,36.266 67.564,36.266 67.508,36.266 67.31,36.068 67.31,25.654 67.056,25.4 60.706,25.4 60.702,25.4 60.452,25.65 60.452,32.258
CS_N on Top Layer "CS_N" (solid, pour order 46): 44.196,55.88 44.196,46.757 44.175,46.736 43.942,46.503 43.942,46.482 33.274,46.482 33.02,46.736 33.02,58.166 33.274,58.42 43.942,58.42 44.196,58.166 44.196,54.102
NetC1_1 on Top Layer "NetC1_1" (solid, pour order 58): 71.998,56.896 70.612,56.896 70.358,57.15 70.358,60.96 70.612,61.214 73.914,61.214 74.422,61.214 74.676,60.96 74.676,57.15 74.422,56.896
SGND on Top Layer "SGND_top" (solid, pour order 61): 78.74,67.056 78.994,67.31 89.154,67.31 96.266,67.31 97.282,67.31 97.536,67.056 97.536,56.134 97.536,55.88 97.282,55.626 88.392,55.626 78.994,55.626 78.74,55.88 78.74,57.912
+VIN on Top Layer "+Vin_top" (solid, pour order 55): 17.78,45.466 36.068,45.466 49.53,45.466 50.546,45.466 50.8,45.212 50.8,44.704 50.8,42.963 50.8,36 50.8,26.4 50.784,26.4 50.546,26.162 48.514,26.162 47.498,26.162 45.974,26.162 36.83,35.306 36.754,35.382 26.924,35.382 17.856,35.382 17.78,35.306
NetC4_1 on Layer2 "NetC4_1" (solid, pour order 56): 60.452,40.35 60.456,40.35 60.706,40.6 60.746,40.64 69.596,40.64 70.104,40.64 70.358,40.894 70.358,55.626 70.612,55.88 77.216,55.88 77.47,55.626 77.47,41.91 77.47,36.576 77.216,36.322 77.16,36.266 67.564,36.266 67.508,36.266 67.31,36.068 67.31,25.654 67.056,25.4 60.706,25.4 60.702,25.4 60.452,25.65 60.452,32.258
SW on Layer2 "SW_L2" (solid, pour order 50): 59.944,47.244 59.944,41.656 60.198,41.402 68.072,41.402 69.596,41.402 69.85,41.656 69.85,48.26 69.85,65.024 69.85,71.374 69.85,73.406 69.596,73.66 60.198,73.66 59.944,73.406 59.944,44.704
SGND on Layer2 "Layer2-SGND" (solid, remove dead copper, pour order 67): 17.78,12.7 17.78,73.66 107.95,73.66 108.331,73.279 108.204,73.152 108.204,12.954 108.077,12.954 107.823,12.7
NetC4_1 on Layer3 "NetC4_1" (solid, pour order 54): 60.452,40.35 60.456,40.35 60.706,40.6 60.746,40.64 69.596,40.64 70.104,40.64 70.358,40.894 70.358,55.626 70.612,55.88 77.216,55.88 77.47,55.626 77.47,41.91 77.47,36.576 77.216,36.322 77.16,36.266 67.564,36.266 67.508,36.266 67.31,36.068 67.31,25.654 67.056,25.4 60.706,25.4 60.702,25.4 60.452,25.65 60.452,32.258
SW on Layer3 "SW_L3" (solid, pour order 49): 59.944,47.244 59.944,41.656 60.198,41.402 68.072,41.402 69.596,41.402 69.85,41.656 69.85,48.26 69.85,65.024 69.85,71.374 69.85,73.406 69.596,73.66 60.198,73.66 59.944,73.406 59.944,44.704
SGND on Layer3 "Layer3-gnd" (solid, remove dead copper, pour order 66): 17.78,12.7 17.78,73.66 107.95,73.66 108.331,73.279 108.204,73.152 108.204,12.954 108.077,12.954 107.823,12.7
NetC4_1 on Bottom Layer "NetC4_1" (solid, pour order 53): 60.452,40.35 60.456,40.35 60.706,40.6 60.746,40.64 69.596,40.64 70.104,40.64 70.358,40.894 70.358,55.626 70.612,55.88 77.216,55.88 77.47,55.626 77.47,41.91 77.47,36.576 77.216,36.322 77.16,36.266 67.564,36.266 67.508,36.266 67.31,36.068 67.31,25.654 67.056,25.4 60.706,25.4 60.702,25.4 60.452,25.65 60.452,32.258
SW on Bottom Layer "SW_L3" (solid, pour order 48): 59.944,47.244 59.944,41.656 60.198,41.402 68.072,41.402 69.596,41.402 69.85,41.656 69.85,48.26 69.85,65.024 69.85,71.374 69.85,73.406 69.596,73.66 60.198,73.66 59.944,73.406 59.944,44.704
SGND on Bottom Layer "Bottom Layer-agnd1" (solid, remove dead copper, pour order 62): 38.608,25.146 29.591,25.146 27.229,27.508 27.229,38.862 30.404,42.037 50.546,42.037 52.07,40.513 52.07,36.703 51.398,36.703 49.62,34.925 49.403,34.925 46.99,32.512 44.958,32.512 44.958,33.909 43.262,35.605 38.608,35.605
SGND on Bottom Layer "Bottom Layer-pgnd-powerpad" (solid, remove dead copper, pour order 63): 39.243,35.306 42.037,35.306 42.291,35.052 42.291,28.067 42.539,27.819 44.958,27.813 45.847,27.051 46.355,26.416 46.355,25.146 39.243,25.146
SGND on Bottom Layer "Bottom Layer-pgnd2" (solid, remove dead copper, pour order 65): 17.78,48.549 17.78,22.479 28.194,22.479 28.829,23.114 25.654,26.289 25.654,27.305 25.654,40.259 28.194,42.799 29.972,44.577 29.972,48.641
SGND on Bottom Layer "Bottom Layer-pgnd" (solid, remove dead copper, pour order 64): 17.78,24.257 38.354,24.257 39.878,25.781 45.736,25.765 45.847,26.035 45.847,31.694 46.045,31.694 47.244,32.893 47.625,32.893 49.022,34.29 49.79,34.29 51.5,36 52.45,36 52.45,36.067 52.959,36.576 52.959,41.021 52.832,41.021 49.149,44.704 17.78,44.704 17.78,73.66 107.95,73.66 107.95,12.7 17.78,12.7

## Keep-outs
Keep-Out Layer:
  lines w0.254: -0.127,0 ccw(c0,0) 0,-0.127 ; -0.127,0 ccw(c0,0) 0,-0.127 ; -0.127,0 ccw(c0,0) 0,-0.127 ; -0.127,0 ccw(c0,0) 0,-0.127 ; -0.127,0 ccw(c0,0) 0,-0.127 ; -0.127,0 ccw(c0,0) 0,-0.127 ; -0.127,87.63 cw(c0,87.63) 0,87.757 ; -0.127,87.63 cw(c0,87.63) 0,87.757 ; -0.127,87.63 cw(c0,87.63) 0,87.757 ; -0.127,87.63 cw(c0,87.63) 0,87.757 ; -0.127,87.63 cw(c0,87.63) 0,87.757 ; -0.127,87.63 cw(c0,87.63) 0,87.757 ; 125.73,87.757 cw(c125.73,87.63) 125.857,87.63 ; 125.73,87.757 cw(c125.73,87.63) 125.857,87.63 ; 125.73,87.757 cw(c125.73,87.63) 125.857,87.63 ; 125.73,87.757 cw(c125.73,87.63) 125.857,87.63 ; 125.73,87.757 cw(c125.73,87.63) 125.857,87.63 ; 125.73,87.757 cw(c125.73,87.63) 125.857,87.63
  text ".Layer_Name" at 14.656,-21.806 h1.52

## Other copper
Top Layer:
  text ".Layer_Name" at 14.656,-21.806 h1.52
Bottom Layer:
  pour cut-out: 32.639,21.463 32.639,24.511 32.766,24.384 34.925,24.384 34.925,21.463
  pour cut-out: 29.337,46.736 29.337,44.45 31.115,44.45 31.115,46.736
  text ".Layer_Name" at 14.656,-21.806 h1.52

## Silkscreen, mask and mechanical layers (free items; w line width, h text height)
Top Overlay:
  text "Texas Instruments" at 18.542,69.596 h1.8
  text "Boost with LM5121" at 80.772,68.58 h1.8
  text ".PRJ_Number" at 19.05,63.5 h1.82
  text ".SCH_Rev" at 32.004,63.5 h1.82
  text "UVLO" at 17.78,50.8 h1.2
  text "VIN" at 17.018,38.608 h1.2 r90
  text "VOUT" at 110.236,38.354 h1.2 r90
  text "GND" at 17.018,27.432 h1.2 r90
  text "GND" at 110.236,27.432 h1.2 r90
  text "AGND" at 31.496,15.494 h1.2
  text "NWAin" at 59.182,10.16 h1.2
  text "VOUT" at 74.676,9.906 h1.2
  text "09/2013" at 19.558,9.398 h1.2
  text ".Layer_Name" at 14.656,-21.806 h1.52
Bottom Overlay:
  text ".Layer_Name" at 14.656,-21.806 h1.52
Top Paste:
  text ".Layer_Name" at 14.656,-21.806 h1.52
Bottom Paste:
  text ".Layer_Name" at 14.656,-21.806 h1.52
Top Solder:
  text ".Layer_Name" at 14.656,-21.806 h1.52
  text ".Layer_Name" at 14.656,-21.806 h1.52
Bottom Solder:
  text ".Layer_Name" at 14.656,-21.806 h1.52
Drill Guide:
  text ".Layer_Name" at 14.656,-21.806 h1.52
M1 Board Outline:
  the board outline again, w0.254
  text ".Layer_Name" at 14.656,-21.806 h1.52
M2 Board Dimensions:
  rectangle: 3.162,-10.427 12.687,-7.252
  rectangle: -0.013,-7.252 3.162,-4.077
  lines w0.178: -0.013,-7.252 25.387,-7.252 ; 3.162,-10.427 3.162,-4.077 ; 6.337,-10.427 6.337,-4.077 ; 12.687,-10.427 12.687,-4.077 ; 19.037,-10.427 19.037,-4.077 ; -0.013,-10.427 -0.013,-4.077 25.387,-4.077 25.387,-10.427 -0.013,-10.427
  lines w0.254: -0.013,-12.078 -0.013,-11.57 ; 1.511,-12.332 -0.013,-11.824 ; 1.511,-11.316 -0.013,-11.824 ; 6.187,-11.824 -0.013,-11.824 ; 19.188,-11.824 25.387,-11.824 ; 23.863,-12.332 25.387,-11.824 ; 23.863,-11.316 25.387,-11.824 ; 25.387,-12.078 25.387,-11.57
  text "25.4 (mm)" at 6.441,-12.738 h1.52
  text ".Layer_Name" at 14.656,-21.806 h1.52
M3 3D STEP Top:
  text ".Layer_Name" at 14.656,-21.806 h1.52
M4 3D STEP Bottom:
  text ".Layer_Name" at 14.656,-21.806 h1.52
M5 Assembly Top:
  lines w0.178: 130.531,2.807 159.106,2.807 ; 130.531,5.918 159.042,5.918 ; 138.532,-0.241 138.532,8.966 ; 148.311,-0.241 130.531,-0.241 ; 148.311,8.966 130.531,8.966 ; 130.531,-0.241 130.531,8.966 ; 130.531,-0.241 159.106,-0.241 159.106,8.966 130.531,8.966
  lines w0.254: -7.417,-23.626 160.223,-23.626 ; -7.417,-18.462 160.274,-18.462 ; -7.417,-13.297 -7.417,-28.791 94.31,-28.791 160.274,-28.791 160.274,-13.297 -7.404,-13.297 -7.404,-28.791 32.614,-28.791 ; 55.194,-28.791 55.194,-13.297 ; 87.376,-18.462 87.376,-13.297 ; 108.712,-18.462 108.712,-13.297 ; 124.511,-28.956 124.511,-23.804
  text "TABLE 1" at 140.373,9.855 h1.02
  text "Variant" at 131.166,7.061 h1.02
  text "Label text" at 142.215,7.061 h1.02
  text "001" at 132.88,4.013 h1.02
  text "ChangeMe!" at 139.929,3.95 h1.02
  text "002" at 132.88,0.838 h1.02
  text "ChangeMe!" at 139.802,0.775 h1.02
  text "COMPONENTS MARKED 'DNP' SHOULD NOT BE POPULATED." at 29.299,-8.09 h1.52
  text "ASSEMBLY VARIANT:" at 29.286,-11.024 h1.52
  text ".VariantName" at 55.601,-11.024 h1.52
  text "PCB VIEWED FROM TOP SIDE" at -5.804,-16.654 h1.52
  text "BOARD #:" at 57.099,-16.654 h1.52
  text ".PRJ_Number" at 70.955,-16.654 h1.52
  text "REV:" at 92.405,-16.654 h1.52
  text ".PCB_Rev" at 99.809,-16.654 h1.52
  text "SVN REV:" at 113.69,-16.654 h1.52
  text ".VersionControl_RevNumber" at 126.543,-16.654 h1.52
  text "IGNORE ->" at -5.804,-21.806 h1.52
  text "PLOT NAME =" at -5.804,-27.034 h1.52
  text ".plot_File_Name" at 14.656,-27.034 h1.52
  text "GENERATED    :" at 57.15,-27.034 h1.52
  text ".Print_Date" at 79.235,-27.034 h1.52
  text ".Print_Time" at 97.752,-27.034 h1.52
  text "TEXAS INSTRUMENTS" at 129.87,-27.034 h1.52
M6 Assembly Bottom:
  lines w0.254: -7.429,-18.474 160.261,-18.474 ; -7.379,-23.639 160.261,-23.639 ; 28.334,-28.969 28.334,-23.817 ; 44.133,-18.474 44.133,-13.31 ; 65.468,-18.474 65.468,-13.31 ; 97.65,-28.804 97.65,-13.31 ; 120.231,-28.804 160.249,-28.804 160.249,-13.31 -7.429,-13.31 -7.429,-28.804 58.534,-28.804 160.261,-28.804 160.261,-13.31
  text "COMPONENTS MARKED 'DNP' SHOULD NOT BE POPULATED." at 154.991,-8.077 h1.52
  text ".VariantName" at 128.473,-11.024 h1.52
  text "ASSEMBLY VARIANT:" at 154.864,-11.024 h1.52
  text ".VersionControl_RevNumber" at 26.302,-16.667 h1.52
  text "SVN REV:" at 39.154,-16.667 h1.52
  text ".PCB_Rev" at 53.035,-16.667 h1.52
  text "REV:" at 60.439,-16.667 h1.52
  text ".PRJ_Number" at 81.89,-16.667 h1.52
  text "BOARD #:" at 95.745,-16.667 h1.52
  text "PCB VIEWED FROM BOTTOM SIDE" at 158.648,-16.667 h1.52
  text "IGNORE ->" at 64.715,-21.806 h1.52
  text "TEXAS INSTRUMENTS" at 22.974,-27.047 h1.52
  text ".Print_Time" at 55.093,-27.047 h1.52
  text ".Print_Date" at 73.609,-27.047 h1.52
  text "GENERATED    :" at 95.694,-27.047 h1.52
  text ".plot_File_Name" at 138.189,-27.047 h1.52
  text "PLOT NAME =" at 158.648,-27.047 h1.52
M9 Title Sheet:
  drawing of 57 lines, arcs and shapes, not listed
  text "1" at 18.792,204.127 h1.78
  text "2" at 82.182,204.127 h1.78
  text "3" at 145.411,204.127 h1.78
  text "4" at 209.08,204.127 h1.78
  text "5" at 272.555,204.127 h1.78
  text "6" at 336.182,204.127 h1.78
  text "A" at -10.579,175.095 h1.78
  text "A" at 365.341,175.095 h1.78
  text "B" at -10.579,114.643 h1.78
  text "B" at 365.341,114.643 h1.78
  text "C" at -10.579,54.318 h1.78
  text "C" at 365.341,54.318 h1.78
  text "PROJECT TITLE:" at 288.125,7.048 h1.14
  text ".PRJ_Title" at 289.395,3.662 h1.78
  text "DESIGNED FOR:" at 288.125,-0.597 h1.14
  text ".PRJ_Customer" at 289.395,-4.153 h1.78
  text "D" at -10.579,-5.88 h1.78
  text "D" at 365.341,-5.88 h1.78
  text "FILE NAME:" at 288.125,-8.217 h1.14
  text ".PCB_File_Name_No_Path" at 289.395,-11.265 h1.78
  text "Texas Instruments (TI) and/or its licensors do not warrant the accuracy or completeness of this specification" at 161.9,-15.376 h1.14
  text "ENGINEER:" at 288.125,-15.583 h1.14
  text "LAYOUT BY:" at 326.352,-15.583 h1.14
  text "or any information contained therein. TI and/or its licensors do not warrant that this design will meet" at 160.757,-18.237 h1.14
  text ".PRJ_Engineer" at 289.395,-19.52 h1.78
  text ".PCB_Layout" at 327.635,-19.52 h1.78
  text "the specifications, will be suitable for your application or fit for any particular purpose, or will operate in" at 160.757,-21.099 h1.14
  text ".Layer_Name" at 14.656,-21.806 h1.52
  text "ALTIUM DESIGNER VERSION:" at 326.352,-23.457 h1.14
  text "an implementation. TI and/or its licensors do not warrant that the design is production worthy. You should" at 160.757,-23.961 h1.14
  text "completely validate and test your design implementation to confirm the system functionality for your application." at 161.9,-26.822 h1.14
  text ".print_Scale" at 289.395,-26.843 h1.78
  text ".Application_BuildNumber" at 327.635,-26.843 h1.78
  text "1" at 18.792,-32.093 h1.78
  text "2" at 82.182,-32.093 h1.78
  text "3" at 145.411,-32.093 h1.78
  text "4" at 209.08,-32.093 h1.78
  text "5" at 272.555,-32.093 h1.78
  text "6" at 336.182,-32.093 h1.78
M10 Fab Notes:
  drawing of 207 lines, arcs and shapes, not listed
  text "DESIGN INFORMATION" at 314.478,172.974 h1.52
  text "(REFER ALSO ARRAY/PANEL PROFILING INFORMATION)" at 305.294,168.866 h1.52
  text "BOARD SIZE" at 287.87,168.758 h1.52
  text "3450MIL" at 299.613,165.511 h1.52
  text "X" at 312.457,165.511 h1.52
  text "4950MIL" at 318.333,165.511 h1.52
  text "Number of Layers :" at 298.106,160.503 h1.52
  text "2" at 325.914,160.249 h1.52
  text "MIN. TRACK WIDTH:" at 298.106,156.972 h1.52
  text "8" at 325.951,156.972 h1.52
  text "MIL" at 329.881,156.972 h1.52
  text "MIN. CLEARANCE:" at 298.106,153.619 h1.52
  text "8" at 325.951,153.619 h1.52
  text "MIL" at 329.881,153.619 h1.52
  text "MIN. VIA PAD SIZE:" at 298.106,150.266 h1.52
  text "24" at 325.189,150.266 h1.52
  text "MIL" at 329.881,150.266 h1.52
  text "0.05mm (2MIL)" at 315.759,146.667 h1.52
  text "MINIMUM ANNULAR RING" at 289.744,146.558 h1.52
  text "EXTERNAL" at 333.742,146.558 h1.52
  text "PER" at 294.824,143.561 h1.52
  text "IPC-D-275 CLASS 2 LEVEL C" at 300.412,143.561 h1.52
  text "MIL, HOLES" at 338.213,140.709 h1.52
  text "+/-" at 328.244,140.691 h1.52
  text "+/-" at 349.936,140.691 h1.52
  text "REGISTRATION TOLERANCES:" at 289.744,140.564 h1.52
  text "METAL" at 320.218,140.564 h1.52
  text "5" at 334.853,140.564 h1.52
  text "3" at 356.012,140.564 h1.52
  text "MIL" at 358.964,140.564 h1.52
  text "MATERIAL:" at 287.844,135.243 h1.52
  text "FR-4 High Tg" at 312.9,131.679 h1.52
  text "FR-4" at 299.554,131.461 h1.52
  text "X" at 309.003,131.461 h1.52
  text "OTHER" at 336.333,131.461 h1.52
  text "62 MIL (1.6mm) +/-10%" at 306.668,127.328 h1.52
  text "THICKNESS:" at 289.744,127.219 h1.52
  text "X" at 303.413,127.219 h1.52
  text "OTHER" at 339.305,127.219 h1.52
  text "TOLERANCE:" at 289.744,123.206 h1.52
  text "X" at 311.062,123.206 h1.52
  text "ANSI IPC-6012 TYPE 3 CLASS 2" at 315.81,123.206 h1.52
  text "OTHER +/-" at 315.81,119.244 h1.52
  text "BOW & TWIST:" at 289.744,115.256 h1.52
  text "X" at 311.062,115.256 h1.52
  text "ANSI IPC-6012 TYPE 3 CLASS 2" at 315.81,115.256 h1.52
  text "OTHER +/-" at 315.81,111.23 h1.52
  text "COPPER THICKNESS (FINISHED):" at 287.844,107.788 h1.52
  text "1.4MIL (1oz)" at 310.196,103.909 h1.52
  text "2MIL (1.4oz)" at 329.678,103.909 h1.52
  text "2.8MIL (2oz)" at 348.144,103.909 h1.52
  text "OUTER:" at 296.912,103.801 h1.52
  text "X" at 306.934,103.784 h1.52
  text "1.4MIL (1oz)" at 310.196,99.922 h1.52
  text "2.8MIL (2oz)" at 329.678,99.922 h1.52
  text "N/A" at 348.132,99.931 h1.52
  text "INNER SIGNAL:" at 289.57,99.813 h1.52
  text "X" at 306.97,99.813 h1.52
  text "DRILLING:" at 287.844,96.282 h1.52
  text "REFERENCE:" at 289.744,93.31 h1.52
  text "X" at 306.209,93.31 h1.52
  text "AS SHOWN" at 310.958,93.31 h1.52
  text "X" at 329.094,93.31 h1.52
  text "NC_DRILL FILES" at 332.574,93.31 h1.52
  text "PTH MIN COPPER THICKNESS:" at 289.744,89.297 h1.52
  text "X" at 324.039,89.297 h1.52
  text "1MIL" at 327.519,89.297 h1.52
  text "OTHER" at 340.143,89.297 h1.52
  text "BOARD FINISH:" at 287.844,85.259 h1.52
  text "SILKSCREEN:" at 291.787,82.261 h1.52
  text "X" at 315.886,82.261 h1.52
  text "TOP" at 319.086,82.261 h1.52
  text "X" at 328.84,82.261 h1.52
  text "BOTTOM" at 332.066,82.261 h1.52
  text "SILKSCREEN COLOR:" at 291.787,78.02 h1.52
  text "X" at 315.86,78.02 h1.52
  text "WHITE" at 319.086,78.02 h1.52
  text "OTHER" at 332.066,78.02 h1.52
  text "SOLDER RESIST COLOR:" at 291.787,73.702 h1.52
  text "X" at 306.208,69.658 h1.52
  text "GREEN" at 309.434,69.658 h1.52
  text "BLUE" at 324.446,69.658 h1.52
  text "OTHER" at 338.111,69.658 h1.52
  text "IMMERSION GOLD (ENIG)" at 314.794,64.87 h1.52
  text "SURFACE FINISH:" at 287.844,64.761 h1.52
  text "X" at 310.045,64.761 h1.52
  text "IMM. TIN/SILVER OR EQUIV" at 296.215,60.773 h1.52
  text "OTHER" at 332.574,60.773 h1.52
  text "ARRAY/PANEL:" at 287.844,56.226 h1.52
  text "CUT AND TRIM PER MECH LAYER 1" at 314.794,56.118 h1.52
  text "N.C. ROUTE" at 314.794,52.264 h1.52
  text "X" at 332.04,52.264 h1.52
  text "V. SCORE" at 336.79,52.264 h1.52
  text "CERTIFICATION:" at 287.844,48.784 h1.52
  text "MATERIALS AND WORKMANSHIP FOR ALL PCBS" at 306.259,48.784 h1.52
  text "TO MEET OR EXCEED THE REQUIREMENTS OF:" at 306.259,46.295 h1.52
  text "X" at 296.773,42.828 h1.52
  text "ANSI IPC-A-600F CLASS ->" at 300.303,42.828 h1.52
  text "X" at 341.935,42.828 h1.52
  text "2" at 344.956,42.828 h1.52
  text "1" at 336.955,42.79 h1.52
  text "3" at 353.948,42.79 h1.52
  text "X" at 296.825,38.777 h1.52
  text "UL 94V-0" at 300.303,38.777 h1.52
  text "X" at 317.45,38.777 h1.52
  text "RoHS" at 320.928,38.777 h1.52
  text "OTHER" at 337.296,38.777 h1.52
  text "PER ORDER" at 347.381,38.777 h1.52
  text "ADDITIONAL REQUIREMENTS:" at 287.844,35.195 h1.52
  text "MICROSECTION:" at 289.744,32.274 h1.52
  text "YES" at 312.749,32.274 h1.52
  text "REQUIRED" at 334.631,28.308 h1.52
  text "BARE BOARD ELEC. TEST:" at 289.744,28.236 h1.52
  text "NONE" at 322.909,28.236 h1.52
  text "X" at 331.405,28.236 h1.52
  text "PER ORDER" at 349.668,28.236 h1.52
  text "MANUFACTURER'S ID/LOGO:" at 289.744,24.248 h1.52
  text "RAIL" at 326.973,24.139 h1.52
  text "X" at 336.485,24.139 h1.52
  text "METAL" at 339.465,24.139 h1.52
  text "SILK" at 352.462,24.139 h1.52
  text ".Layer_Name" at 14.656,-21.806 h1.52
M11 Gerber Information:
  lines w0.254: -7.417,-23.626 160.223,-23.626 ; -7.417,-18.462 160.274,-18.462 ; -7.417,-13.297 -7.417,-28.791 94.31,-28.791 160.274,-28.791 160.274,-13.297 -7.404,-13.297 -7.404,-28.791 32.614,-28.791 ; 55.194,-28.791 55.194,-13.297 ; 87.376,-18.462 87.376,-13.297 ; 108.712,-18.462 108.712,-13.297 ; 124.511,-28.956 124.511,-23.804
  text "ALL ARTWORK VIEWED FROM TOP SIDE" at -5.804,-16.654 h1.52
  text "BOARD #:" at 57.099,-16.654 h1.52
  text ".PRJ_Number" at 70.955,-16.654 h1.52
  text "REV:" at 92.405,-16.654 h1.52
  text ".PCB_Rev" at 99.809,-16.654 h1.52
  text "SVN REV:" at 113.69,-16.654 h1.52
  text ".VersionControl_RevNumber" at 126.543,-16.654 h1.52
  text "LAYER NAME =" at -5.804,-21.806 h1.52
  text "PLOT NAME =" at -5.804,-27.034 h1.52
  text ".plot_File_Name" at 14.656,-27.034 h1.52
  text "GENERATED    :" at 57.15,-27.034 h1.52
  text ".Print_Date" at 79.235,-27.034 h1.52
  text ".Print_Time" at 97.752,-27.034 h1.52
  text "TEXAS INSTRUMENTS" at 129.87,-27.034 h1.52
M12 Stackup:
  lines w0.152: 288.544,189.484 353.314,189.484 ; 288.544,192.136 353.314,192.136 ; 287.02,177.165 ccw(c287.884,177.165) 287.884,176.301 353.974,176.301 ccw(c353.974,177.165) 354.838,177.165 354.838,195.097 ccw(c353.974,195.097) 353.974,195.961 287.884,195.961 ccw(c287.884,195.097) 287.02,195.097 287.02,177.165
  text "The Stackup Legend below this is static." at 294.78,200.012 h1.52
  text "If you change the stackup, update the Legend." at 295.034,197.726 h1.52
  text "Layer Stack Up Detail for: Ref_Design.PcbDoc" at 288.544,192.966 h1.45
  text "Layer" at 288.544,191.145 h0.61
  text "Gerber" at 311.298,191.145 h0.61
  text "Copper" at 325.611,191.145 h0.61
  text "Dielectric" at 340.92,191.145 h0.61
  text "Name" at 288.544,189.926 h0.61
  text "Document" at 311.298,189.926 h0.61
  text "Thickness" at 325.611,189.926 h0.61
  text "Material" at 340.92,189.926 h0.61
  text "Top Solder Mask" at 288.544,187.565 h0.86
  text "(.GTS)" at 311.298,187.565 h0.86
  text "Solder Resist" at 340.92,187.565 h0.86
  text "Top Layer" at 288.544,185.107 h0.86
  text "(.GTL)" at 311.298,185.107 h0.86
  text "1.4mil" at 325.611,185.107 h0.86
  text "FR-4" at 340.92,183.879 h0.86
  text "Bottom Layer" at 288.544,182.65 h0.86
  text "(.GBL)" at 311.298,182.65 h0.86
  text "1.4mil" at 325.611,182.65 h0.86
  text "Bottom Solder Mask" at 288.544,180.192 h0.86
  text "(.GBS)" at 311.298,180.192 h0.86
  text "Solder Resist" at 340.92,180.192 h0.86
  text ".Layer_Name" at 14.656,-21.806 h1.52
M13 Component Bodies Top:
  text ".Layer_Name" at 14.656,-21.806 h1.52
M14 Component Bodies Bottom:
  text ".Layer_Name" at 14.656,-21.806 h1.52
M15 Courtyards Top:
  text ".Layer_Name" at 14.656,-21.806 h1.52
M16 Courtyards Bottom:
  text ".Layer_Name" at 14.656,-21.806 h1.52
Drill Drawing:
  text ".Layer_Name" at 14.656,-21.806 h1.52

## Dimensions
111.76,82.042 to 15.24,83.058 on M2 Board Dimensions
12.954,7.62 to 8.89,76.2 on M2 Board Dimensions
